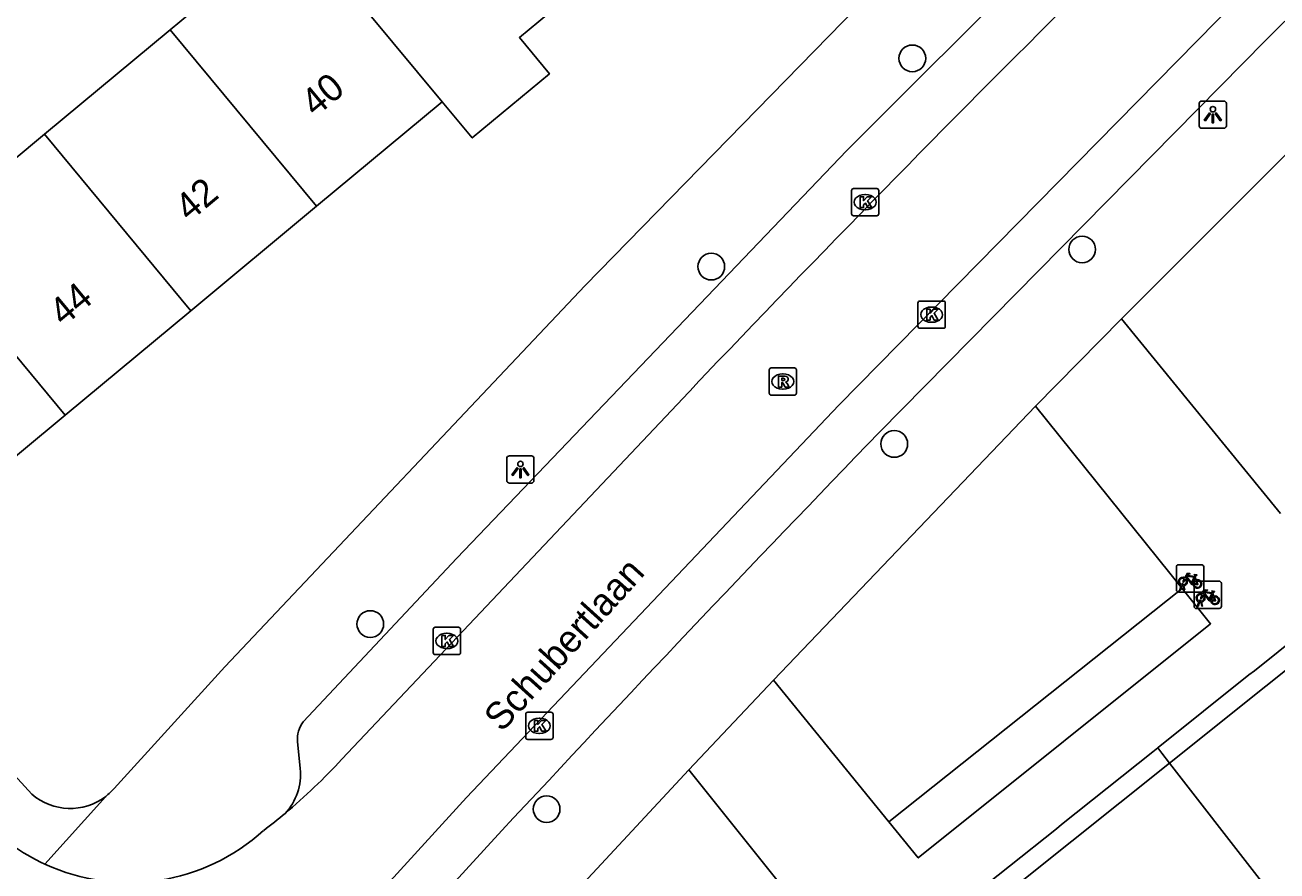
# Model space of a CAD drawing. Extents: x 159040 to 160094, y 381214 to 382518.
# Drawn here: x 159665.82 to 159711.7, y 381858.06 to 381889.05 of the extents above; entities that cross this region are included whole.
import ezdxf

# ---------------------------------------------------------------- set-up
doc = ezdxf.new("R2010")
doc.units = 0
for name, color, linetype in [('IMGEO_Boom', 7, 'Continuous'), ('IMGEO_Fietsenrek', 7, 'Continuous'), ('IMGEO_Haag', 7, 'Continuous'), ('IMGEO_Kolk', 7, 'Continuous'), ('IMGEO_Lichtpunt', 7, 'Continuous'), ('IMGEO_Openbare_ruimte_label', 7, 'Continuous'), ('IMGEO_Pand', 7, 'Continuous'), ('IMGEO_Pand_nummerreeks', 7, 'Continuous'), ('IMGEO_Pand_overbouw', 7, 'Continuous'), ('IMGEO_Rijbaan_lokaal_open', 7, 'Continuous'), ('IMGEO_Rioolput', 7, 'Continuous'), ('IMGEO_Voetpad_open', 7, 'Continuous')]:
    doc.layers.add(name, color=color, linetype=linetype)

msp = doc.modelspace()

# ---------------------------------------------------------------- linework, layer by layer
at = {"layer": 'IMGEO_Boom'}
for centre in [(159698.336, 381887.831), (159704.559, 381880.83), (159690.969, 381880.2), (159697.675, 381873.703), (159678.473, 381867.104), (159684.935, 381860.323)]:
    msp.add_circle(centre, 0.489, dxfattribs=at)
at = {"layer": 'IMGEO_Fietsenrek'}
for p, q in [((159708.014, 381868.351), (159708.014, 381869.192)), ((159708.014, 381869.192), (159708.014, 381868.351)), ((159708.089, 381869.276), (159708.93, 381869.276)), ((159708.93, 381869.276), (159708.089, 381869.276)), ((159709.014, 381869.201), (159709.014, 381868.36)), ((159709.014, 381868.36), (159709.014, 381869.201)), ((159708.141, 381868.36), (159708.18, 381868.52)), ((159708.21, 381868.508), (159708.175, 381868.36)), ((159708.252, 381868.532), (159708.251, 381868.536)), ((159708.293, 381868.36), (159708.259, 381868.502)), ((159708.283, 381868.543), (159708.284, 381868.536)), ((159708.291, 381868.506), (159708.326, 381868.36)), ((159708.661, 381867.749), (159708.661, 381868.59)), ((159708.661, 381868.59), (159708.661, 381867.749)), ((159708.701, 381868.825), (159708.737, 381868.73)), ((159708.736, 381868.674), (159709.577, 381868.674)), ((159709.577, 381868.674), (159708.736, 381868.674)), ((159709.661, 381868.599), (159709.661, 381867.758)), ((159709.661, 381867.758), (159709.661, 381868.599)), ((159708.939, 381868.276), (159708.098, 381868.276)), ((159708.098, 381868.276), (159708.939, 381868.276)), ((159708.175, 381868.36), (159708.141, 381868.36)), ((159708.326, 381868.36), (159708.293, 381868.36)), ((159709.348, 381868.223), (159709.384, 381868.128)), ((159709.586, 381867.674), (159708.745, 381867.674)), ((159708.745, 381867.674), (159709.586, 381867.674)), ((159708.788, 381867.758), (159708.827, 381867.918)), ((159708.822, 381867.758), (159708.788, 381867.758)), ((159708.857, 381867.906), (159708.822, 381867.758)), ((159708.899, 381867.93), (159708.898, 381867.934)), ((159708.94, 381867.758), (159708.906, 381867.9)), ((159708.93, 381867.941), (159708.931, 381867.934)), ((159708.938, 381867.904), (159708.973, 381867.758)), ((159708.973, 381867.758), (159708.94, 381867.758))]:
    msp.add_line(p, q, dxfattribs=at)
for points in [[(159708.327, 381868.802), (159708.422, 381868.966), (159708.508, 381868.952), (159708.51, 381868.943), (159708.454, 381868.932), (159708.427, 381868.887), (159708.683, 381868.846)], [(159708.683, 381868.846), (159708.708, 381868.895), (159708.702, 381868.899), (159708.679, 381868.903), (159708.667, 381868.91), (159708.666, 381868.913), (159708.668, 381868.918), (159708.763, 381868.903), (159708.765, 381868.893), (159708.755, 381868.88), (159708.743, 381868.874), (159708.729, 381868.88), (159708.701, 381868.825)], [(159708.348, 381868.75), (159708.296, 381868.66), (159708.256, 381868.635), (159708.257, 381868.682), (159708.312, 381868.776)], [(159708.623, 381868.558), (159708.573, 381868.558), (159708.382, 381868.809), (159708.363, 381868.777)], [(159708.67, 381868.821), (159708.413, 381868.862), (159708.396, 381868.833), (159708.563, 381868.613), (159708.67, 381868.821)], [(159708.718, 381868.723), (159708.688, 381868.8), (159708.579, 381868.582), (159708.622, 381868.582)], [(159708.652, 381868.582), (159708.772, 381868.581), (159708.728, 381868.695)], [(159708.748, 381868.702), (159708.803, 381868.557), (159708.653, 381868.557)], [(159708.995, 381868.148), (159708.943, 381868.058), (159708.903, 381868.033), (159708.904, 381868.08), (159708.959, 381868.174)], [(159708.974, 381868.2), (159709.069, 381868.364), (159709.155, 381868.35), (159709.157, 381868.341), (159709.101, 381868.33), (159709.074, 381868.285), (159709.33, 381868.244)], [(159709.27, 381867.956), (159709.22, 381867.956), (159709.029, 381868.207), (159709.01, 381868.175)], [(159709.317, 381868.219), (159709.06, 381868.26), (159709.043, 381868.231), (159709.21, 381868.011), (159709.317, 381868.219)], [(159709.365, 381868.121), (159709.335, 381868.198), (159709.226, 381867.98), (159709.269, 381867.98)], [(159709.299, 381867.98), (159709.419, 381867.979), (159709.375, 381868.093)], [(159709.395, 381868.1), (159709.45, 381867.955), (159709.3, 381867.955)], [(159709.33, 381868.244), (159709.355, 381868.293), (159709.349, 381868.297), (159709.326, 381868.301), (159709.314, 381868.308), (159709.313, 381868.311), (159709.315, 381868.316), (159709.41, 381868.301), (159709.412, 381868.291), (159709.402, 381868.278), (159709.39, 381868.272), (159709.376, 381868.278), (159709.348, 381868.223)]]:
    msp.add_lwpolyline(points, dxfattribs=at)
for centre, radius, start, end in [((159708.092, 381869.198), 0.0779, 92.4484, 184.2845), ((159708.092, 381869.198), 0.0779, 92.4484, 184.2845), ((159708.936, 381869.198), 0.0779, 2.4484, 94.2845), ((159708.936, 381869.198), 0.0779, 2.4484, 94.2845), ((159708.254, 381868.661), 0.159, 62.6766, 242.1369), ((159708.254, 381868.661), 0.129, 63.3192, 238.903), ((159708.234, 381868.532), 0.0499, 12.8025, 158.6934), ((159708.254, 381868.661), 0.159, 253.9967, 271.7867), ((159708.234, 381868.532), 0.0174, 12.8025, 163.4502), ((159708.254, 381868.661), 0.129, 253.415, 269.0204), ((159708.254, 381868.661), 0.129, 283.6043, 43.4302), ((159708.254, 381868.661), 0.159, 283.5766, 46.6042), ((159708.781, 381868.577), 0.159, 113.3408, 178.3217), ((159708.781, 381868.577), 0.159, 187.0065, 105.7708), ((159708.781, 381868.577), 0.129, 113.923, 177.9556), ((159708.781, 381868.577), 0.129, 188.6715, 104.5883), ((159708.739, 381868.596), 0.0779, 92.4484, 184.2845), ((159708.739, 381868.596), 0.0779, 92.4484, 184.2845), ((159709.583, 381868.596), 0.0779, 2.4484, 94.2845), ((159709.583, 381868.596), 0.0779, 2.4484, 94.2845), ((159708.092, 381868.354), 0.0779, 182.4484, 274.2845), ((159708.092, 381868.354), 0.0779, 182.4484, 274.2845), ((159708.901, 381868.059), 0.159, 62.6766, 242.1369), ((159708.901, 381868.059), 0.129, 63.3192, 238.903), ((159708.881, 381867.93), 0.0499, 12.8025, 158.6934), ((159708.901, 381868.059), 0.129, 283.6043, 43.4302), ((159708.901, 381868.059), 0.159, 283.5766, 46.6042), ((159708.936, 381868.354), 0.0779, 272.4484, 4.2845), ((159708.936, 381868.354), 0.0779, 272.4484, 4.2845), ((159709.428, 381867.975), 0.159, 113.3408, 178.3217), ((159709.428, 381867.975), 0.159, 187.0065, 105.7708), ((159709.428, 381867.975), 0.129, 113.923, 177.9556), ((159709.428, 381867.975), 0.129, 188.6715, 104.5883), ((159708.739, 381867.752), 0.0779, 182.4484, 274.2845), ((159708.739, 381867.752), 0.0779, 182.4484, 274.2845), ((159708.901, 381868.059), 0.159, 253.9967, 271.7867), ((159708.881, 381867.93), 0.0174, 12.8025, 163.4502), ((159708.901, 381868.059), 0.129, 253.415, 269.0204), ((159709.583, 381867.752), 0.0779, 272.4484, 4.2845), ((159709.583, 381867.752), 0.0779, 272.4484, 4.2845)]:
    msp.add_arc(centre, radius, start, end, dxfattribs=at)
at = {"layer": 'IMGEO_Haag'}
msp.add_lwpolyline([(159697.478, 381859.857), (159708.224, 381868.411)], dxfattribs=at)
at = {"layer": 'IMGEO_Kolk'}
for p, q in [((159696.107, 381882.136), (159696.107, 381882.988)), ((159696.182, 381883.062), (159697.034, 381883.062)), ((159696.595, 381882.842), (159696.62, 381882.842)), ((159697.108, 381882.988), (159697.108, 381882.136)), ((159696.618, 381882.282), (159696.593, 381882.282)), ((159697.034, 381882.062), (159696.182, 381882.062)), ((159698.543, 381878.014), (159698.543, 381878.866)), ((159698.618, 381878.94), (159699.47, 381878.94)), ((159699.031, 381878.72), (159699.056, 381878.72)), ((159699.544, 381878.866), (159699.544, 381878.014)), ((159699.054, 381878.16), (159699.029, 381878.16)), ((159699.47, 381877.94), (159698.618, 381877.94)), ((159680.778, 381866.059), (159680.778, 381866.911)), ((159680.853, 381866.985), (159681.705, 381866.985)), ((159681.266, 381866.765), (159681.291, 381866.765)), ((159681.779, 381866.911), (159681.779, 381866.059)), ((159681.289, 381866.205), (159681.264, 381866.205)), ((159681.705, 381865.985), (159680.853, 381865.985)), ((159684.242, 381863.875), (159685.094, 381863.875)), ((159684.167, 381862.949), (159684.167, 381863.801)), ((159684.655, 381863.655), (159684.68, 381863.655)), ((159685.168, 381863.801), (159685.168, 381862.949)), ((159684.678, 381863.095), (159684.653, 381863.095)), ((159685.094, 381862.875), (159684.242, 381862.875))]:
    msp.add_line(p, q, dxfattribs=at)
for points in [[(159696.107, 381882.136), (159696.107, 381882.988)], [(159696.182, 381883.062), (159697.034, 381883.062)], [(159696.428, 381882.762), (159696.551, 381882.762), (159696.551, 381882.611), (159696.681, 381882.762), (159696.845, 381882.762), (159696.699, 381882.611), (159696.852, 381882.362), (159696.7, 381882.362), (159696.615, 381882.526), (159696.551, 381882.459), (159696.551, 381882.362), (159696.428, 381882.362), (159696.428, 381882.762)], [(159697.108, 381882.988), (159697.108, 381882.136)], [(159697.034, 381882.062), (159696.182, 381882.062)], [(159698.543, 381878.014), (159698.543, 381878.866)], [(159698.618, 381878.94), (159699.47, 381878.94)], [(159698.864, 381878.64), (159698.987, 381878.64), (159698.987, 381878.489), (159699.117, 381878.64), (159699.281, 381878.64), (159699.135, 381878.489), (159699.288, 381878.24), (159699.136, 381878.24), (159699.051, 381878.404), (159698.987, 381878.337), (159698.987, 381878.24), (159698.864, 381878.24), (159698.864, 381878.64)], [(159699.544, 381878.866), (159699.544, 381878.014)], [(159699.47, 381877.94), (159698.618, 381877.94)], [(159680.778, 381866.059), (159680.778, 381866.911)], [(159680.853, 381866.985), (159681.705, 381866.985)], [(159681.099, 381866.685), (159681.222, 381866.685), (159681.222, 381866.534), (159681.352, 381866.685), (159681.516, 381866.685), (159681.37, 381866.534), (159681.523, 381866.285), (159681.371, 381866.285), (159681.286, 381866.449), (159681.222, 381866.382), (159681.222, 381866.285), (159681.099, 381866.285), (159681.099, 381866.685)], [(159681.779, 381866.911), (159681.779, 381866.059)], [(159681.705, 381865.985), (159680.853, 381865.985)], [(159684.242, 381863.875), (159685.094, 381863.875)], [(159684.167, 381862.949), (159684.167, 381863.801)], [(159684.488, 381863.575), (159684.611, 381863.575), (159684.611, 381863.424), (159684.741, 381863.575), (159684.905, 381863.575), (159684.759, 381863.424), (159684.912, 381863.175), (159684.76, 381863.175), (159684.675, 381863.339), (159684.611, 381863.272), (159684.611, 381863.175), (159684.488, 381863.175), (159684.488, 381863.575)], [(159685.168, 381863.801), (159685.168, 381862.949)], [(159685.094, 381862.875), (159684.242, 381862.875)]]:
    msp.add_lwpolyline(points, dxfattribs=at)
for centre, start, end in [((159696.184, 381882.986), 91.552, 178.448), ((159696.184, 381882.986), 91.552, 178.448), ((159697.032, 381882.986), 1.552, 88.448), ((159697.032, 381882.986), 1.552, 88.448), ((159696.184, 381882.138), 181.552, 268.448), ((159696.184, 381882.138), 181.552, 268.448), ((159697.032, 381882.138), 271.552, 358.448), ((159697.032, 381882.138), 271.552, 358.448), ((159698.62, 381878.864), 91.552, 178.448), ((159698.62, 381878.864), 91.552, 178.448), ((159699.468, 381878.864), 1.552, 88.448), ((159699.468, 381878.864), 1.552, 88.448), ((159698.62, 381878.016), 181.552, 268.448), ((159698.62, 381878.016), 181.552, 268.448), ((159699.468, 381878.016), 271.552, 358.448), ((159699.468, 381878.016), 271.552, 358.448), ((159680.855, 381866.909), 91.552, 178.448), ((159680.855, 381866.909), 91.552, 178.448), ((159681.703, 381866.909), 1.552, 88.448), ((159681.703, 381866.909), 1.552, 88.448), ((159680.855, 381866.061), 181.552, 268.448), ((159680.855, 381866.061), 181.552, 268.448), ((159681.703, 381866.061), 271.552, 358.448), ((159681.703, 381866.061), 271.552, 358.448), ((159684.244, 381863.799), 91.552, 178.448), ((159684.244, 381863.799), 91.552, 178.448), ((159685.092, 381863.799), 1.552, 88.448), ((159685.092, 381863.799), 1.552, 88.448), ((159684.244, 381862.951), 181.552, 268.448), ((159684.244, 381862.951), 181.552, 268.448), ((159685.092, 381862.951), 271.552, 358.448), ((159685.092, 381862.951), 271.552, 358.448)]:
    msp.add_arc(centre, 0.0765, start, end, dxfattribs=at)
for centre, major_axis, ratio, start_param, end_param in [((159696.594, 381882.562), (-0.387, 0.002), 0.722429, 4.712389, 7.853982), ((159696.619, 381882.562), (-0.39, 0.002), 0.717154, 1.570796, 4.712389), ((159699.03, 381878.44), (-0.387, 0.002), 0.722429, 4.712389, 7.853982), ((159699.055, 381878.44), (-0.39, 0.002), 0.717154, 1.570796, 4.712389), ((159681.265, 381866.485), (-0.387, 0.002), 0.722429, 4.712389, 7.853982), ((159681.29, 381866.485), (-0.39, 0.002), 0.717154, 1.570796, 4.712389), ((159684.654, 381863.375), (-0.387, 0.002), 0.722429, 4.712389, 7.853982), ((159684.679, 381863.375), (-0.39, 0.002), 0.717154, 1.570796, 4.712389)]:
    msp.add_ellipse(centre, major_axis=major_axis, ratio=ratio, start_param=start_param, end_param=end_param, dxfattribs=at)
at = {"layer": 'IMGEO_Lichtpunt'}
for p, q in [((159708.85, 381886.171), (159708.85, 381885.364)), ((159708.85, 381886.171), (159708.85, 381885.364)), ((159709.752, 381886.266), (159708.944, 381886.266)), ((159709.752, 381886.266), (159708.944, 381886.266)), ((159709.846, 381885.364), (159709.846, 381886.171)), ((159709.846, 381885.364), (159709.846, 381886.171)), ((159708.944, 381885.27), (159709.752, 381885.27)), ((159708.944, 381885.27), (159709.752, 381885.27)), ((159683.475, 381873.173), (159683.475, 381872.366)), ((159683.475, 381873.173), (159683.475, 381872.366)), ((159684.377, 381873.268), (159683.569, 381873.268)), ((159684.377, 381873.268), (159683.569, 381873.268)), ((159684.471, 381872.366), (159684.471, 381873.173)), ((159684.471, 381872.366), (159684.471, 381873.173)), ((159683.569, 381872.272), (159684.377, 381872.272)), ((159683.569, 381872.272), (159684.377, 381872.272))]:
    msp.add_line(p, q, dxfattribs=at)
for points in [[(159709.224, 381885.835), (159709.263, 381885.807), (159709.075, 381885.545), (159709.037, 381885.572), (159709.224, 381885.835)], [(159709.326, 381885.787), (159709.373, 381885.787), (159709.373, 381885.465), (159709.326, 381885.465), (159709.326, 381885.787)], [(159709.436, 381885.807), (159709.474, 381885.834), (159709.661, 381885.572), (159709.622, 381885.544), (159709.436, 381885.807)], [(159683.849, 381872.837), (159683.888, 381872.809), (159683.7, 381872.547), (159683.662, 381872.574), (159683.849, 381872.837)], [(159683.951, 381872.789), (159683.998, 381872.789), (159683.998, 381872.467), (159683.951, 381872.467), (159683.951, 381872.789)], [(159684.061, 381872.809), (159684.099, 381872.836), (159684.286, 381872.574), (159684.247, 381872.546), (159684.061, 381872.809)]]:
    msp.add_lwpolyline(points, dxfattribs=at)
for centre in [(159709.349, 381885.969), (159683.974, 381872.971)]:
    msp.add_circle(centre, 0.0994, dxfattribs=at)
for centre, start, end in [((159708.944, 381886.171), 90, 180), ((159708.944, 381886.171), 90, 180), ((159709.752, 381886.171), 0, 90), ((159709.752, 381886.171), 0, 90), ((159708.944, 381885.364), 180, 270), ((159708.944, 381885.364), 180, 270), ((159709.752, 381885.364), 270, 0), ((159709.752, 381885.364), 270, 360), ((159683.569, 381873.173), 90, 180), ((159683.569, 381873.173), 90, 180), ((159684.377, 381873.173), 0, 90), ((159684.377, 381873.173), 0, 90), ((159683.569, 381872.366), 180, 270), ((159683.569, 381872.366), 180, 270), ((159684.377, 381872.366), 270, 0), ((159684.377, 381872.366), 270, 360)]:
    msp.add_arc(centre, 0.0946, start, end, dxfattribs=at)
at = {"layer": 'IMGEO_Pand'}
for points in [[(159671.135, 381888.874), (159675.741, 381892.7)], [(159675.741, 381892.7), (159681.108, 381886.24)], [(159685.714, 381890.067), (159683.938, 381888.591), (159685.038, 381887.267), (159682.208, 381884.916), (159681.108, 381886.24)], [(159666.529, 381885.047), (159671.135, 381888.874)], [(159676.503, 381882.413), (159671.135, 381888.874)], [(159681.108, 381886.24), (159676.503, 381882.413)], [(159661.924, 381881.22), (159666.529, 381885.047)], [(159671.897, 381878.586), (159666.529, 381885.047)], [(159667.292, 381874.76), (159662.551, 381870.821), (159659.205, 381874.848), (159658.492, 381874.255), (159656.606, 381876.524), (159656.499, 381876.653), (159654.289, 381879.311), (159659.743, 381883.844), (159661.924, 381881.22)], [(159676.503, 381882.413), (159671.897, 381878.586)], [(159667.292, 381874.76), (159661.924, 381881.22)], [(159671.897, 381878.586), (159667.292, 381874.76)], [(159721.632, 381873.983), (159721.518, 381873.896), (159721.948, 381873.339), (159707.762, 381862.012)], [(159707.762, 381862.012), (159693.382, 381850.53)], [(159714.07, 381853.886), (159707.762, 381862.012)]]:
    msp.add_lwpolyline(points, dxfattribs=at)
at = {"layer": 'IMGEO_Pand_overbouw'}
for points in [[(159707.762, 381862.012), (159721.948, 381873.339), (159721.518, 381873.896), (159718.097, 381871.164), (159717.909, 381871.014), (159714.481, 381868.278), (159714.288, 381868.123), (159710.871, 381865.396), (159710.674, 381865.239), (159707.341, 381862.578), (159707.33, 381862.569), (159707.483, 381862.371)], [(159707.762, 381862.012), (159707.483, 381862.371), (159707.33, 381862.569), (159707.144, 381862.421), (159703.805, 381859.755), (159703.616, 381859.604), (159700.179, 381856.86), (159699.984, 381856.705), (159696.57, 381853.979), (159696.371, 381853.821), (159693.046, 381851.167), (159692.943, 381851.084), (159693.099, 381850.888), (159693.382, 381850.53)]]:
    msp.add_lwpolyline(points, close=True, dxfattribs=at)
at = {"layer": 'IMGEO_Rijbaan_lokaal_open'}
for points in [[(159668.847, 381846.275), (159670.932, 381848.62), (159681.996, 381860.747), (159695.645, 381875.129), (159710.23, 381889.95)], [(159690.35, 381875.826), (159677.432, 381862.151)]]:
    msp.add_lwpolyline(points, dxfattribs=at)
for centre, radius, start, end in [((160204.447, 381386.408), 709.807, 134.795301, 136.408748), ((159659.998, 381878.353), 23.8, 310.1691, 317.0984), ((159666.252, 381870.878), 14.055, 306.2626, 310.3414), ((159669.621, 381864.959), 7.326, 223.0405, 245.2128), ((159669.625, 381864.96), 7.329, 245.1812, 312.3777)]:
    msp.add_arc(centre, radius, start, end, dxfattribs=at)
at = {"layer": 'IMGEO_Rioolput'}
for p, q in [((159693.089, 381875.563), (159693.089, 381876.415)), ((159693.164, 381876.489), (159694.016, 381876.489)), ((159693.577, 381876.269), (159693.602, 381876.269)), ((159694.09, 381876.415), (159694.09, 381875.563)), ((159694.016, 381875.489), (159693.164, 381875.489)), ((159693.6, 381875.709), (159693.575, 381875.709))]:
    msp.add_line(p, q, dxfattribs=at)
for points in [[(159693.089, 381875.563), (159693.089, 381876.415)], [(159693.164, 381876.489), (159694.016, 381876.489)], [(159694.09, 381876.415), (159694.09, 381875.563)], [(159693.678, 381876.187), (159693.426, 381876.189), (159693.426, 381875.789)], [(159693.426, 381875.789), (159693.55, 381875.789), (159693.55, 381875.951), (159693.561, 381875.951)], [(159693.604, 381876.108), (159693.55, 381876.108), (159693.55, 381876.027)], [(159693.55, 381876.027), (159693.602, 381876.027)], [(159693.608, 381875.922), (159693.679, 381875.789), (159693.819, 381875.789), (159693.754, 381875.915)], [(159694.016, 381875.489), (159693.164, 381875.489)]]:
    msp.add_lwpolyline(points, dxfattribs=at)
for centre, radius, start, end in [((159693.166, 381876.413), 0.0765, 91.552, 178.448), ((159693.166, 381876.413), 0.0765, 91.552, 178.448), ((159694.014, 381876.413), 0.0765, 1.552, 88.448), ((159694.014, 381876.413), 0.0765, 1.552, 88.448), ((159693.56, 381875.898), 0.0533, 26.0293, 88.6989), ((159693.586, 381876.216), 0.19, 274.7715, 282.9687), ((159693.61, 381876.012), 0.0964, 77.0061, 93.1865), ((159693.624, 381876.069), 0.0378, 276.6634, 79.6772), ((159693.677, 381876.077), 0.109, 350.3612, 89.416), ((159693.675, 381876.077), 0.112, 277.5842, 350.9817), ((159693.659, 381875.862), 0.108, 29.5134, 73.7905), ((159693.166, 381875.565), 0.0765, 181.552, 268.448), ((159693.166, 381875.565), 0.0765, 181.552, 268.448), ((159694.014, 381875.565), 0.0765, 271.552, 358.448), ((159694.014, 381875.565), 0.0765, 271.552, 358.448)]:
    msp.add_arc(centre, radius, start, end, dxfattribs=at)
for centre, major_axis, ratio, start_param, end_param in [((159693.576, 381875.989), (-0.387, 0.002), 0.722429, 4.712389, 7.853982), ((159693.601, 381875.989), (-0.39, 0.002), 0.717154, 1.570796, 4.712389)]:
    msp.add_ellipse(centre, major_axis=major_axis, ratio=ratio, start_param=start_param, end_param=end_param, dxfattribs=at)
at = {"layer": 'IMGEO_Voetpad_open'}
for points in [[(159669.087, 381861.079), (159673.142, 381865.54), (159686.348, 381879.508), (159698.411, 381891.866), (159710.875, 381904.23), (159719.353, 381912.382), (159724.085, 381916.847), (159733.97, 381925.903)], [(159676.013, 381863.527), (159681.646, 381869.517), (159695.937, 381884.457), (159709.782, 381898.284)], [(159706.005, 381878.291), (159719.769, 381892.076)], [(159712.706, 381889.901), (159711.279, 381888.487), (159697.132, 381874.129)], [(159646.785, 381881.967), (159666.065, 381860.87)], [(159702.847, 381875.088), (159706.005, 381878.291)], [(159711.824, 381871.157), (159706.005, 381878.291)], [(159693.246, 381865.049), (159702.847, 381875.088)], [(159702.847, 381875.088), (159708.224, 381868.411)], [(159708.224, 381868.411), (159709.268, 381867.114), (159698.555, 381858.536), (159697.478, 381859.857)], [(159690.142, 381861.769), (159693.246, 381865.049)], [(159697.478, 381859.857), (159693.246, 381865.049)], [(159675.903, 381861.808), (159675.803, 381862.799)], [(159680.679, 381851.58), (159690.142, 381861.769)], [(159690.142, 381861.769), (159693.903, 381857.065)], [(159666.549, 381858.308), (159668.777, 381860.786)], [(159683.298, 381859.538), (159672.219, 381847.437)]]:
    msp.add_lwpolyline(points, dxfattribs=at)
for centre, radius, start, end in [((160376.748, 381215.919), 946.107, 135.916676, 137.134347), ((159676.945, 381862.864), 1.144, 144.567, 183.2514), ((159673.85, 381861.585), 2.065, 316.5799, 6.1946), ((159667.473, 381862.514), 2.165, 229.4151, 307.0367), ((159666.618, 381863.381), 3.375, 309.7624, 317.0078)]:
    msp.add_arc(centre, radius, start, end, dxfattribs=at)

# ---------------------------------------------------------------- texts
at = {"layer": 'IMGEO_Openbare_ruimte_label'}
msp.add_text('Schubertlaan', height=1, rotation=47.8766, dxfattribs=at).set_placement((159683.294, 381863.11))
at = {"layer": 'IMGEO_Pand_nummerreeks'}
for s, p in [('40', (159676.46, 381885.654)), ('42', (159671.841, 381881.816)), ('44', (159667.228, 381877.983))]:
    msp.add_text(s, height=1, rotation=39.7222, dxfattribs=at).set_placement(p)

doc.saveas('drawing.dxf')
